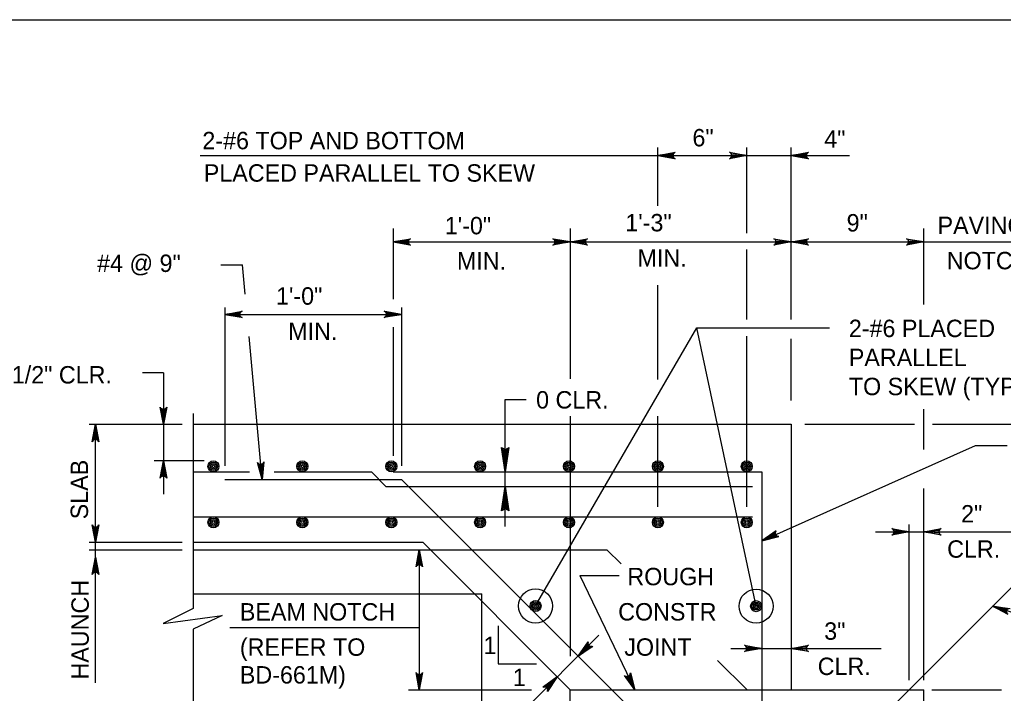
# Model space of a CAD drawing. Extents: x 638653 to 642302, y 298557 to 300414.
# Drawn here: x 640118.2 to 640287.7, y 299613.5 to 299729.5 of the extents above; entities that cross this region are included whole.
import ezdxf

# ---------------------------------------------------------------- set-up
doc = ezdxf.new("R2010")
doc.units = 0
doc.layers.add('1', color=7, linetype='Continuous')

msp = doc.modelspace()

# ---------------------------------------------------------------- linework, layer by layer
at = {"layer": '1'}
for p, q in [((639863.16, 299729.52), (640649.16, 299729.52)), ((640228.15, 299697.45), (640228.15, 299707.5)), ((640243.47, 299692.77), (640243.47, 299707.5)), ((640251.13, 299677.86), (640251.13, 299707.5)), ((640149.29, 299706.12), (640261.19, 299706.12)), ((640182.55, 299693.58), (640182.55, 299681.4)), ((640213.03, 299693.58), (640213.03, 299667.65)), ((640273.99, 299680.44), (640273.99, 299693.58)), ((640182.55, 299691.25), (640213.03, 299691.25)), ((640213.03, 299691.25), (640251.13, 299691.25)), ((640251.13, 299691.25), (640292.75, 299691.25)), ((640243.47, 299677.86), (640243.47, 299689.95)), ((640152.84, 299687.27), (640156.59, 299687.27)), ((640157.05, 299682.27), (640156.59, 299687.27)), ((640228.15, 299667.55), (640228.15, 299683.81)), ((640153.51, 299679.97), (640153.51, 299652.67)), ((640153.51, 299678.77), (640183.99, 299678.77)), ((640183.99, 299679.97), (640183.99, 299652.67)), ((640159.99, 299650.34), (640157.72, 299674.97)), ((640182.55, 299676.57), (640182.55, 299654.42)), ((640207.07, 299628.54), (640234.85, 299676.44)), ((640234.85, 299676.44), (640257.71, 299676.44)), ((640245.08, 299628.51), (640234.85, 299676.44)), ((640243.47, 299645.6), (640243.47, 299675.01)), ((640251.13, 299663.94), (640251.13, 299674.54)), ((640142.95, 299668.69), (640139.35, 299668.69)), ((640142.95, 299668.69), (640142.95, 299647.79)), ((640201.86, 299642.22), (640201.86, 299664.1)), ((640201.86, 299664.1), (640205.43, 299664.1)), ((640148.1, 299661.67), (640148.1, 299628.08)), ((640273.99, 299655.52), (640273.99, 299662.43)), ((640130.13, 299659.83), (640146.16, 299659.83)), ((640131.24, 299639.51), (640131.24, 299659.83)), ((640148.1, 299659.83), (640251.13, 299659.83)), ((640213.03, 299661.24), (640213.03, 299619.9)), ((640228.15, 299645.6), (640228.15, 299661.25)), ((640251.13, 299659.83), (640251.13, 299614.11)), ((640253.46, 299659.83), (640272.37, 299659.83)), ((640275.45, 299659.83), (640356.29, 299659.83)), ((640246.05, 299639.78), (640282.86, 299656.2)), ((640282.86, 299656.2), (640288.33, 299656.2)), ((640149.95, 299653.54), (640141.35, 299653.54)), ((640148.1, 299651.63), (640157.78, 299651.63)), ((640162.06, 299651.63), (640178.78, 299651.63)), ((640178.78, 299651.63), (640181.29, 299649.12)), ((640182.55, 299651.63), (640246.05, 299651.63)), ((640246.05, 299651.63), (640246.05, 299583.63)), ((640153.51, 299650.34), (640183.99, 299650.34)), ((640256.61, 299577.71), (640183.99, 299650.34)), ((640181.29, 299649.12), (640244.43, 299649.12)), ((640273.99, 299615.76), (640273.99, 299648.77)), ((640240.92, 299583.57), (640303.84, 299646.5)), ((640148.1, 299643.91), (640244.43, 299643.91)), ((640265.67, 299641.32), (640288.96, 299641.32)), ((640271.45, 299615.76), (640271.45, 299642.57)), ((640130.13, 299639.51), (640146.16, 299639.51)), ((640131.24, 299615.32), (640131.24, 299639.51)), ((640148.1, 299639.51), (640187.63, 299639.51)), ((640213.03, 299614.11), (640187.63, 299639.51)), ((640130.13, 299638.24), (640146.16, 299638.24)), ((640148.1, 299638.24), (640188.9, 299638.24)), ((640187.04, 299638.24), (640187.04, 299614.11)), ((640188.9, 299638.24), (640219.38, 299638.24)), ((640221.8, 299635.82), (640219.38, 299638.24)), ((640214.73, 299633.77), (640224.2, 299614.11)), ((640214.73, 299633.77), (640221.46, 299633.77)), ((640148.1, 299630.62), (640197.79, 299630.62)), ((640197.79, 299590.73), (640197.79, 299630.62)), ((640307.83, 299621.35), (640285.84, 299628.5)), ((640148.1, 299624.56), (640148.1, 299599.6)), ((640154.42, 299624.82), (640187.04, 299624.82)), ((640200.65, 299625.13), (640200.65, 299618.55)), ((640218, 299623.5), (640205.1, 299610.6)), ((640240.75, 299621.24), (640266.64, 299621.24)), ((640243.51, 299614.11), (640238.44, 299619.17)), ((640200.65, 299618.55), (640207.23, 299618.55)), ((640185.2, 299614.11), (640206.35, 299614.11)), ((640213.03, 299614.11), (640251.13, 299614.11)), ((640213.03, 299554.98), (640213.03, 299614.11)), ((640251.13, 299614.11), (640273.99, 299614.11)), ((640273.99, 299554.98), (640273.99, 299614.11)), ((640275.38, 299614.11), (640287.38, 299614.11))]:
    msp.add_line(p, q, dxfattribs=at)
for points in [[(640228.15, 299706.12), (640231.14, 299706.68), (640231.02, 299706.6), (640230.91, 299706.52), (640230.85, 299706.42), (640230.79, 299706.32), (640230.77, 299706.22), (640230.75, 299706.12), (640230.77, 299706.02), (640230.79, 299705.92), (640230.85, 299705.82), (640230.91, 299705.72), (640231.02, 299705.64), (640231.14, 299705.56), (640228.15, 299706.12), (640231.02, 299705.64), (640230.91, 299705.72), (640228.15, 299706.12), (640230.85, 299705.82), (640230.79, 299705.92), (640228.15, 299706.12), (640230.77, 299706.02), (640230.75, 299706.12), (640228.15, 299706.12), (640230.77, 299706.22), (640230.79, 299706.32), (640228.15, 299706.12), (640230.85, 299706.42), (640230.91, 299706.52), (640228.15, 299706.12), (640231.02, 299706.6)], [(640243.47, 299706.12), (640240.49, 299705.56), (640240.72, 299705.72), (640240.84, 299705.92), (640240.87, 299706.12), (640240.84, 299706.32), (640240.72, 299706.52), (640240.49, 299706.68), (640243.47, 299706.12), (640240.72, 299706.52), (640240.84, 299706.32), (640243.47, 299706.12), (640240.87, 299706.12), (640240.84, 299705.92), (640243.47, 299706.12), (640240.72, 299705.72)], [(640251.13, 299706.12), (640254.11, 299706.68), (640254, 299706.6), (640253.88, 299706.52), (640253.82, 299706.42), (640253.76, 299706.32), (640253.75, 299706.22), (640253.73, 299706.12), (640253.75, 299706.02), (640253.76, 299705.92), (640253.82, 299705.82), (640253.88, 299705.72), (640254, 299705.64), (640254.11, 299705.56), (640251.13, 299706.12), (640254, 299705.64), (640253.88, 299705.72), (640251.13, 299706.12), (640253.82, 299705.82), (640253.76, 299705.92), (640251.13, 299706.12), (640253.75, 299706.02), (640253.73, 299706.12), (640251.13, 299706.12), (640253.75, 299706.22), (640253.76, 299706.32), (640251.13, 299706.12), (640253.82, 299706.42), (640253.88, 299706.52), (640251.13, 299706.12), (640254, 299706.6)], [(640182.55, 299691.25), (640185.53, 299691.8), (640185.42, 299691.72), (640185.3, 299691.65), (640185.24, 299691.55), (640185.18, 299691.45), (640185.17, 299691.35), (640185.15, 299691.25), (640185.17, 299691.15), (640185.18, 299691.05), (640185.24, 299690.95), (640185.3, 299690.85), (640185.42, 299690.77), (640185.53, 299690.69), (640182.55, 299691.25), (640185.42, 299690.77), (640185.3, 299690.85), (640182.55, 299691.25), (640185.24, 299690.95), (640185.18, 299691.05), (640182.55, 299691.25), (640185.17, 299691.15), (640185.15, 299691.25), (640182.55, 299691.25), (640185.17, 299691.35), (640185.18, 299691.45), (640182.55, 299691.25), (640185.24, 299691.55), (640185.3, 299691.65), (640182.55, 299691.25), (640185.42, 299691.72)], [(640213.03, 299691.25), (640210.05, 299690.69), (640210.16, 299690.77), (640210.28, 299690.85), (640210.34, 299690.95), (640210.39, 299691.05), (640210.41, 299691.15), (640210.43, 299691.25), (640210.41, 299691.35), (640210.39, 299691.45), (640210.34, 299691.55), (640210.28, 299691.65), (640210.16, 299691.72), (640210.05, 299691.8), (640213.03, 299691.25), (640210.16, 299691.72), (640210.28, 299691.65), (640213.03, 299691.25), (640210.34, 299691.55), (640210.39, 299691.45), (640213.03, 299691.25), (640210.41, 299691.35), (640210.43, 299691.25), (640213.03, 299691.25), (640210.41, 299691.15), (640210.39, 299691.05), (640213.03, 299691.25), (640210.34, 299690.95), (640210.28, 299690.85), (640213.03, 299691.25), (640210.16, 299690.77)], [(640213.03, 299691.25), (640216.01, 299691.8), (640215.78, 299691.65), (640215.66, 299691.45), (640215.63, 299691.25), (640215.66, 299691.05), (640215.78, 299690.85), (640216.01, 299690.69), (640213.03, 299691.25), (640215.78, 299690.85), (640215.66, 299691.05), (640213.03, 299691.25), (640215.63, 299691.25), (640215.66, 299691.45), (640213.03, 299691.25), (640215.78, 299691.65)], [(640251.13, 299691.25), (640248.15, 299690.69), (640248.38, 299690.85), (640248.49, 299691.05), (640248.53, 299691.25), (640248.49, 299691.45), (640248.38, 299691.65), (640248.15, 299691.8), (640251.13, 299691.25), (640248.38, 299691.65), (640248.49, 299691.45), (640251.13, 299691.25), (640248.53, 299691.25), (640248.49, 299691.05), (640251.13, 299691.25), (640248.38, 299690.85)], [(640251.13, 299691.25), (640254.11, 299691.8), (640253.88, 299691.65), (640253.76, 299691.45), (640253.73, 299691.25), (640253.76, 299691.05), (640253.88, 299690.85), (640254.11, 299690.69), (640251.13, 299691.25), (640253.88, 299690.85), (640253.76, 299691.05), (640251.13, 299691.25), (640253.73, 299691.25), (640253.76, 299691.45), (640251.13, 299691.25), (640253.88, 299691.65)], [(640273.99, 299691.25), (640271.01, 299690.69), (640271.24, 299690.85), (640271.35, 299691.05), (640271.39, 299691.25), (640271.35, 299691.45), (640271.24, 299691.65), (640271.01, 299691.8), (640273.99, 299691.25), (640271.24, 299691.65), (640271.35, 299691.45), (640273.99, 299691.25), (640271.39, 299691.25), (640271.35, 299691.05), (640273.99, 299691.25), (640271.24, 299690.85)], [(640153.51, 299678.77), (640156.49, 299679.32), (640156.37, 299679.24), (640156.26, 299679.17), (640156.2, 299679.07), (640156.14, 299678.97), (640156.12, 299678.87), (640156.11, 299678.77), (640156.12, 299678.67), (640156.14, 299678.57), (640156.2, 299678.47), (640156.26, 299678.37), (640156.37, 299678.29), (640156.49, 299678.21), (640153.51, 299678.77), (640156.37, 299678.29), (640156.26, 299678.37), (640153.51, 299678.77), (640156.2, 299678.47), (640156.14, 299678.57), (640153.51, 299678.77), (640156.12, 299678.67), (640156.11, 299678.77), (640153.51, 299678.77), (640156.12, 299678.87), (640156.14, 299678.97), (640153.51, 299678.77), (640156.2, 299679.07), (640156.26, 299679.17), (640153.51, 299678.77), (640156.37, 299679.24)], [(640183.99, 299678.77), (640181, 299678.21), (640181.12, 299678.29), (640181.23, 299678.37), (640181.29, 299678.47), (640181.35, 299678.57), (640181.37, 299678.67), (640181.39, 299678.77), (640181.37, 299678.87), (640181.35, 299678.97), (640181.29, 299679.07), (640181.23, 299679.17), (640181.12, 299679.24), (640181, 299679.32), (640183.99, 299678.77), (640181.12, 299679.24), (640181.23, 299679.17), (640183.99, 299678.77), (640181.29, 299679.07), (640181.35, 299678.97), (640183.99, 299678.77), (640181.37, 299678.87), (640181.39, 299678.77), (640183.99, 299678.77), (640181.37, 299678.67), (640181.35, 299678.57), (640183.99, 299678.77), (640181.29, 299678.47), (640181.23, 299678.37), (640183.99, 299678.77), (640181.12, 299678.29)], [(640142.95, 299659.83), (640142.39, 299662.81), (640142.47, 299662.69), (640142.55, 299662.58), (640142.65, 299662.52), (640142.75, 299662.46), (640142.85, 299662.44), (640142.95, 299662.43), (640143.05, 299662.44), (640143.15, 299662.46), (640143.25, 299662.52), (640143.35, 299662.58), (640143.43, 299662.69), (640143.51, 299662.81), (640142.95, 299659.83), (640143.43, 299662.69), (640143.35, 299662.58), (640142.95, 299659.83), (640143.25, 299662.52), (640143.15, 299662.46), (640142.95, 299659.83), (640143.05, 299662.44), (640142.95, 299662.43), (640142.95, 299659.83), (640142.85, 299662.44), (640142.75, 299662.46), (640142.95, 299659.83), (640142.65, 299662.52), (640142.55, 299662.58), (640142.95, 299659.83), (640142.47, 299662.69)], [(640131.24, 299659.83), (640131.8, 299656.84), (640131.72, 299656.96), (640131.64, 299657.07), (640131.54, 299657.13), (640131.44, 299657.19), (640131.34, 299657.21), (640131.24, 299657.23), (640131.14, 299657.21), (640131.04, 299657.19), (640130.94, 299657.13), (640130.84, 299657.07), (640130.76, 299656.96), (640130.68, 299656.84), (640131.24, 299659.83), (640130.76, 299656.96), (640130.84, 299657.07), (640131.24, 299659.83), (640130.94, 299657.13), (640131.04, 299657.19), (640131.24, 299659.83), (640131.14, 299657.21), (640131.24, 299657.23), (640131.24, 299659.83), (640131.34, 299657.21), (640131.44, 299657.19), (640131.24, 299659.83), (640131.54, 299657.13), (640131.64, 299657.07), (640131.24, 299659.83), (640131.72, 299656.96)], [(640202.33, 299655.7), (640202.01, 299655.54), (640201.86, 299651.63), (640202.33, 299655.7), (640202.48, 299655.85), (640201.86, 299651.63), (640201.7, 299655.54), (640201.39, 299655.7), (640201.86, 299651.63), (640201.23, 299655.85), (640201.39, 299655.7)], [(640142.95, 299653.54), (640143.51, 299650.56), (640143.43, 299650.67), (640143.35, 299650.79), (640143.25, 299650.85), (640143.15, 299650.91), (640143.05, 299650.92), (640142.95, 299650.94), (640142.85, 299650.92), (640142.75, 299650.91), (640142.65, 299650.85), (640142.55, 299650.79), (640142.47, 299650.67), (640142.39, 299650.56), (640142.95, 299653.54), (640142.47, 299650.67), (640142.55, 299650.79), (640142.95, 299653.54), (640142.65, 299650.85), (640142.75, 299650.91), (640142.95, 299653.54), (640142.85, 299650.92), (640142.95, 299650.94), (640142.95, 299653.54), (640143.05, 299650.92), (640143.15, 299650.91), (640142.95, 299653.54), (640143.25, 299650.85), (640143.35, 299650.79), (640142.95, 299653.54), (640143.43, 299650.67)], [(640159.99, 299650.34), (640159.16, 299653.25), (640159.25, 299653.15), (640159.34, 299653.04), (640159.44, 299652.99), (640159.55, 299652.94), (640159.65, 299652.93), (640159.75, 299652.92), (640159.85, 299652.95), (640159.95, 299652.98), (640160.04, 299653.04), (640160.14, 299653.11), (640160.2, 299653.23), (640160.27, 299653.36), (640159.99, 299650.34), (640160.2, 299653.23), (640160.14, 299653.11), (640159.99, 299650.34), (640160.04, 299653.04), (640159.95, 299652.98), (640159.99, 299650.34), (640159.85, 299652.95), (640159.75, 299652.92), (640159.99, 299650.34), (640159.65, 299652.93), (640159.55, 299652.94), (640159.99, 299650.34), (640159.44, 299652.99), (640159.34, 299653.04), (640159.99, 299650.34), (640159.25, 299653.15)], [(640201.39, 299645.06), (640201.7, 299645.21), (640201.86, 299649.12), (640201.39, 299645.06), (640201.23, 299644.9), (640201.86, 299649.12), (640202.01, 299645.21), (640202.33, 299645.06), (640201.86, 299649.12), (640202.48, 299644.9), (640202.33, 299645.06)], [(640131.24, 299639.51), (640130.68, 299642.49), (640130.76, 299642.37), (640130.84, 299642.26), (640130.94, 299642.2), (640131.04, 299642.14), (640131.14, 299642.12), (640131.24, 299642.11), (640131.34, 299642.12), (640131.44, 299642.14), (640131.54, 299642.2), (640131.64, 299642.26), (640131.72, 299642.37), (640131.8, 299642.49), (640131.24, 299639.51), (640131.72, 299642.37), (640131.64, 299642.26), (640131.24, 299639.51), (640131.54, 299642.2), (640131.44, 299642.14), (640131.24, 299639.51), (640131.34, 299642.12), (640131.24, 299642.11), (640131.24, 299639.51), (640131.14, 299642.12), (640131.04, 299642.14), (640131.24, 299639.51), (640130.94, 299642.2), (640130.84, 299642.26), (640131.24, 299639.51), (640130.76, 299642.37)], [(640246.05, 299639.78), (640249, 299640.48), (640248.86, 299640.51), (640248.73, 299640.53), (640248.63, 299640.6), (640248.54, 299640.67), (640248.48, 299640.75), (640248.42, 299640.84), (640248.4, 299640.94), (640248.37, 299641.03), (640248.39, 299641.15), (640248.4, 299641.26), (640248.47, 299641.38), (640248.54, 299641.5), (640246.05, 299639.78), (640248.47, 299641.38), (640248.4, 299641.26), (640246.05, 299639.78), (640248.39, 299641.15), (640248.37, 299641.03), (640246.05, 299639.78), (640248.4, 299640.94), (640248.42, 299640.84), (640246.05, 299639.78), (640248.48, 299640.75), (640248.54, 299640.67), (640246.05, 299639.78), (640248.63, 299640.6), (640248.73, 299640.53), (640246.05, 299639.78), (640248.86, 299640.51)], [(640271.45, 299641.32), (640268.47, 299640.76), (640268.7, 299640.92), (640268.82, 299641.12), (640268.85, 299641.32), (640268.82, 299641.52), (640268.7, 299641.72), (640268.47, 299641.88), (640271.45, 299641.32), (640268.7, 299641.72), (640268.82, 299641.52), (640271.45, 299641.32), (640268.85, 299641.32), (640268.82, 299641.12), (640271.45, 299641.32), (640268.7, 299640.92)], [(640273.99, 299641.32), (640276.97, 299641.88), (640276.74, 299641.72), (640276.62, 299641.52), (640276.59, 299641.32), (640276.62, 299641.12), (640276.74, 299640.92), (640276.97, 299640.76), (640273.99, 299641.32), (640276.74, 299640.92), (640276.62, 299641.12), (640273.99, 299641.32), (640276.59, 299641.32), (640276.62, 299641.52), (640273.99, 299641.32), (640276.74, 299641.72)], [(640187.04, 299638.24), (640187.6, 299635.26), (640187.52, 299635.37), (640187.44, 299635.49), (640187.34, 299635.54), (640187.24, 299635.6), (640187.14, 299635.62), (640187.04, 299635.64), (640186.94, 299635.62), (640186.84, 299635.6), (640186.74, 299635.54), (640186.64, 299635.49), (640186.56, 299635.37), (640186.48, 299635.26), (640187.04, 299638.24), (640186.56, 299635.37), (640186.64, 299635.49), (640187.04, 299638.24), (640186.74, 299635.54), (640186.84, 299635.6), (640187.04, 299638.24), (640186.94, 299635.62), (640187.04, 299635.64), (640187.04, 299638.24), (640187.14, 299635.62), (640187.24, 299635.6), (640187.04, 299638.24), (640187.34, 299635.54), (640187.44, 299635.49), (640187.04, 299638.24), (640187.52, 299635.37)], [(640131.24, 299636.97), (640131.8, 299633.98), (640131.72, 299634.1), (640131.64, 299634.21), (640131.54, 299634.27), (640131.44, 299634.33), (640131.34, 299634.35), (640131.24, 299634.37), (640131.14, 299634.35), (640131.04, 299634.33), (640130.94, 299634.27), (640130.84, 299634.21), (640130.76, 299634.1), (640130.68, 299633.98), (640131.24, 299636.97), (640130.76, 299634.1), (640130.84, 299634.21), (640131.24, 299636.97), (640130.94, 299634.27), (640131.04, 299634.33), (640131.24, 299636.97), (640131.14, 299634.35), (640131.24, 299634.37), (640131.24, 299636.97), (640131.34, 299634.35), (640131.44, 299634.33), (640131.24, 299636.97), (640131.54, 299634.27), (640131.64, 299634.21), (640131.24, 299636.97), (640131.72, 299634.1)], [(640148.1, 299628.08), (640142.92, 299625.54), (640153.07, 299626.92), (640148.1, 299624.56)], [(640285.84, 299628.5), (640288.85, 299628.13)], [(640288.51, 299627.06), (640285.84, 299628.5), (640288.43, 299627.17)], [(640288.34, 299627.28), (640285.84, 299628.5), (640288.32, 299627.39)], [(640288.29, 299627.51), (640285.84, 299628.5), (640288.3, 299627.61)], [(640288.32, 299627.71), (640285.84, 299628.5), (640288.36, 299627.8)], [(640288.41, 299627.89), (640285.84, 299628.5), (640288.5, 299627.97)], [(640288.58, 299628.04), (640285.84, 299628.5), (640288.72, 299628.08)], [(640214.41, 299619.91), (640216.16, 299622.39), (640216.13, 299622.25), (640216.1, 299622.12), (640216.13, 299622), (640216.16, 299621.89), (640216.22, 299621.81), (640216.27, 299621.72), (640216.36, 299621.66), (640216.44, 299621.6), (640216.55, 299621.57), (640216.66, 299621.54), (640216.8, 299621.57), (640216.94, 299621.59), (640214.41, 299619.91), (640216.8, 299621.57), (640216.66, 299621.54), (640214.41, 299619.91), (640216.55, 299621.57), (640216.44, 299621.6), (640214.41, 299619.91), (640216.36, 299621.66), (640216.27, 299621.72), (640214.41, 299619.91), (640216.22, 299621.81), (640216.16, 299621.89), (640214.41, 299619.91), (640216.13, 299622), (640216.1, 299622.12), (640214.41, 299619.91), (640216.13, 299622.25)], [(640246.05, 299621.24), (640243.07, 299620.68), (640243.3, 299620.84), (640243.41, 299621.04), (640243.45, 299621.24), (640243.41, 299621.44), (640243.3, 299621.64), (640243.07, 299621.8), (640246.05, 299621.24), (640243.3, 299621.64), (640243.41, 299621.44), (640246.05, 299621.24), (640243.45, 299621.24), (640243.41, 299621.04), (640246.05, 299621.24), (640243.3, 299620.84)], [(640251.13, 299621.24), (640254.11, 299621.8), (640253.88, 299621.64), (640253.76, 299621.44), (640253.73, 299621.24), (640253.76, 299621.04), (640253.88, 299620.84), (640254.11, 299620.68), (640251.13, 299621.24), (640253.88, 299620.84), (640253.76, 299621.04), (640251.13, 299621.24), (640253.73, 299621.24), (640253.76, 299621.44), (640251.13, 299621.24), (640253.88, 299621.64)], [(640187.04, 299614.11), (640186.48, 299617.09), (640186.56, 299616.97), (640186.64, 299616.86), (640186.74, 299616.8), (640186.84, 299616.74), (640186.94, 299616.72), (640187.04, 299616.71), (640187.14, 299616.72), (640187.24, 299616.74), (640187.34, 299616.8), (640187.44, 299616.86), (640187.52, 299616.97), (640187.6, 299617.09), (640187.04, 299614.11), (640187.52, 299616.97), (640187.44, 299616.86), (640187.04, 299614.11), (640187.34, 299616.8), (640187.24, 299616.74), (640187.04, 299614.11), (640187.14, 299616.72), (640187.04, 299616.71), (640187.04, 299614.11), (640186.94, 299616.72), (640186.84, 299616.74), (640187.04, 299614.11), (640186.74, 299616.8), (640186.64, 299616.86), (640187.04, 299614.11), (640186.56, 299616.97)], [(640210.82, 299616.32), (640209.14, 299613.79), (640209.16, 299613.93), (640209.18, 299614.07), (640209.15, 299614.18), (640209.12, 299614.29), (640209.06, 299614.37), (640209, 299614.46), (640208.92, 299614.51), (640208.84, 299614.57), (640208.72, 299614.6), (640208.61, 299614.63), (640208.47, 299614.6), (640208.34, 299614.57), (640210.82, 299616.32), (640208.47, 299614.6), (640208.61, 299614.63), (640210.82, 299616.32), (640208.72, 299614.6), (640208.84, 299614.57), (640210.82, 299616.32), (640208.92, 299614.51), (640209, 299614.46), (640210.82, 299616.32), (640209.06, 299614.37), (640209.12, 299614.29), (640210.82, 299616.32), (640209.15, 299614.18), (640209.18, 299614.07), (640210.82, 299616.32), (640209.16, 299613.93)], [(640224.2, 299614.11), (640222.4, 299616.55), (640222.52, 299616.48), (640222.65, 299616.41), (640222.76, 299616.4), (640222.88, 299616.39), (640222.98, 299616.42), (640223.07, 299616.45), (640223.16, 299616.51), (640223.24, 299616.57), (640223.3, 299616.66), (640223.37, 299616.76), (640223.39, 299616.9), (640223.41, 299617.04), (640224.2, 299614.11), (640223.39, 299616.9), (640223.37, 299616.76), (640224.2, 299614.11), (640223.3, 299616.66), (640223.24, 299616.57), (640224.2, 299614.11), (640223.16, 299616.51), (640223.07, 299616.45), (640224.2, 299614.11), (640222.98, 299616.42), (640222.88, 299616.39), (640224.2, 299614.11), (640222.76, 299616.4), (640222.65, 299616.41), (640224.2, 299614.11), (640222.52, 299616.48)]]:
    msp.add_lwpolyline(points, dxfattribs=at)
for centre, radius in [((640151.57, 299652.59), 0.952), ((640151.57, 299652.59), 0.714), ((640151.57, 299652.59), 0.476), ((640166.89, 299652.59), 0.952), ((640166.89, 299652.59), 0.714), ((640166.89, 299652.59), 0.476), ((640182.21, 299652.59), 0.952), ((640182.21, 299652.59), 0.714), ((640182.21, 299652.59), 0.476), ((640197.52, 299652.59), 0.952), ((640197.52, 299652.59), 0.714), ((640197.52, 299652.59), 0.476), ((640212.84, 299652.59), 0.952), ((640212.84, 299652.59), 0.714), ((640212.84, 299652.59), 0.476), ((640228.15, 299652.59), 0.952), ((640228.15, 299652.59), 0.714), ((640228.15, 299652.59), 0.476), ((640243.47, 299652.59), 0.952), ((640243.47, 299652.59), 0.714), ((640243.47, 299652.59), 0.476), ((640151.57, 299652.59), 0.238), ((640166.89, 299652.59), 0.238), ((640182.21, 299652.59), 0.238), ((640197.52, 299652.59), 0.238), ((640212.84, 299652.59), 0.238), ((640228.15, 299652.59), 0.238), ((640243.47, 299652.59), 0.238), ((640151.57, 299642.96), 0.952), ((640151.57, 299642.96), 0.714), ((640151.57, 299642.96), 0.476), ((640151.57, 299642.96), 0.238), ((640166.89, 299642.96), 0.952), ((640166.89, 299642.96), 0.714), ((640166.89, 299642.96), 0.476), ((640166.89, 299642.96), 0.238), ((640182.21, 299642.96), 0.952), ((640182.21, 299642.96), 0.714), ((640182.21, 299642.96), 0.476), ((640182.21, 299642.96), 0.238), ((640197.52, 299642.96), 0.952), ((640197.52, 299642.96), 0.714), ((640197.52, 299642.96), 0.476), ((640197.52, 299642.96), 0.238), ((640212.84, 299642.96), 0.952), ((640212.84, 299642.96), 0.714), ((640212.84, 299642.96), 0.476), ((640212.84, 299642.96), 0.238), ((640228.15, 299642.96), 0.952), ((640228.15, 299642.96), 0.714), ((640228.15, 299642.96), 0.476), ((640228.15, 299642.96), 0.238), ((640243.47, 299642.96), 0.952), ((640243.47, 299642.96), 0.714), ((640243.47, 299642.96), 0.476), ((640243.47, 299642.96), 0.238), ((640207.07, 299628.54), 2.94), ((640245.08, 299628.51), 2.94), ((640207.07, 299628.54), 0.952), ((640207.07, 299628.54), 0.714), ((640245.08, 299628.51), 0.952), ((640245.08, 299628.51), 0.714), ((640207.07, 299628.54), 0.476), ((640207.07, 299628.54), 0.238), ((640245.08, 299628.51), 0.476), ((640245.08, 299628.51), 0.238)]:
    msp.add_circle(centre, radius, dxfattribs=at)

# ---------------------------------------------------------------- texts
for s, p in [('6"', (640234.11, 299707.7)), ('2-#6 TOP AND BOTTOM', (640149.66, 299707.2)), ('4"', (640256.82, 299707.47)), ('PLACED PARALLEL TO SKEW', (640149.91, 299701.62)), ('1\'-0"', (640191.43, 299692.55)), ('1\'-3"', (640222.54, 299693.06)), ('9"', (640260.68, 299693.04)), ('PAVING', (640276.35, 299692.6)), ('#4 @ 9"', (640131.52, 299686.07)), ('MIN.', (640193.53, 299686.48)), ('MIN.', (640224.64, 299686.99)), ('NOTCH', (640277.93, 299686.53)), ('1\'-0"', (640162.35, 299680.43)), ('MIN.', (640164.45, 299674.36)), ('2-#6 PLACED', (640261.06, 299674.85)), ('PARALLEL', (640261.06, 299669.85)), ('2 1/2" CLR.', (640113.47, 299666.86)), ('TO SKEW (TYP.)', (640261.06, 299664.85)), ('0 CLR.', (640207.17, 299662.55)), ('2"', (640280.4, 299642.92)), ('CLR.', (640278, 299636.85)), ('ROUGH', (640222.9, 299632.11)), ('BEAM NOTCH', (640156.12, 299626.03)), ('CONSTR', (640221.31, 299626.04)), (' 3"', (640255.7, 299622.72)), ('(REFER TO', (640156.12, 299619.96)), ('1', (640198.09, 299620.25)), (' JOINT', (640221.25, 299619.97)), ('CLR.', (640255.7, 299616.65)), ('BD-661M)', (640156.12, 299615.18)), ('1', (640203.14, 299614.74))]:
    msp.add_text(s, height=3, dxfattribs=at).set_placement(p)
for s, p in [('SLAB', (640129.96, 299643.47)), ('HAUNCH', (640130.09, 299615.87))]:
    msp.add_text(s, height=3, rotation=90, dxfattribs=at).set_placement(p)

doc.saveas('drawing.dxf')
